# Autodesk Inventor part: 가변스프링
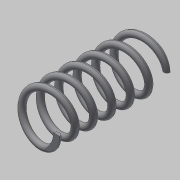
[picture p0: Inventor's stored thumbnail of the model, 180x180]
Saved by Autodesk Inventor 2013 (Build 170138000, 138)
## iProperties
Created: 2020-02
Part Number: 가변스프링
Material: 일반
Document SubType Name: Modeling
Designer: Administrator
Density: 1 g/cm^3
Mass: 0.819169 g
Surface Area: 16.6083 cm^2
Volume: 0.819169 cm^3
Author: Administrator
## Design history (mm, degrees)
sketch "스케치1"
  geometry: L1 (0, 0)-(7, 0); L2 (7, 0)-(7, 35.5); L3 (7, 35.5)-(0, 35.5); L4 (0, 35.5)-(0, 0); C1 r 1 at (7, 0)
  constraints: 8 end point, 2 parallel, 1 centre point, 1 coincident, 1 horizontal, 1 perpendicular
  dimensions: "d0" = 2 diameter of C1; "d2" = 14 diameter of L2 L4; "d3" = 35.5 distance of L1.end L2.end (derived)
feature "코일1" sketch "스케치1" pitch "d4" = 10; turns "d6" = 6; dims "d5" = 35.5 (= d3), "d7" = 0, angle "d8" = 90 deg, angle "d9" = 90 deg, "d10" = 0, "d11" = 0
sketch "스케치2"
  geometry: L1 (35.5, 9)-(0, 9); L2 (0, 9)-(0, -9); L3 (0, -9)-(35.5, -9); L4 (35.5, -9)-(35.5, 9); 2 further points
  constraints: 8 end point, 2 parallel, 1 coincident, 1 horizontal, 1 midpoint, 1 perpendicular
  dimensions: "d12" = 35.5 distance of L2.end L3.end (derived); "d14" = 18 distance of L3.end L1.start
extrude "돌출1" sketch "스케치2" stored distance "d15" = 18; taper "d16" = 0 deg
node "솔리드1"
